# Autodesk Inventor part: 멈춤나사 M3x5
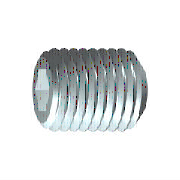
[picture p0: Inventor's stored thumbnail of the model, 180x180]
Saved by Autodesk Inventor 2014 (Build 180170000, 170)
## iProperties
Created: 2012-02
Part Number: 멈춤나사 M3x5
Material: 강철, 연강
Description: 6각 소켓 머리 없는 멈춤 나사
Document SubType Name: Modeling
Standard: KS B 1028
Designer: mduedu
Standards Organization: KS
Language: ko-KR
Size Designation: 납작점M3x5
Categories: <MemberInstance><Categories><Category DisplayName="조임쇠" InternalName="e4da775c-781d-43d5-af7c-5136215cf5a6" Mnemonic="FSTN"><Category DisplayName="볼트" InternalN
Density: 1 g/cm^3
Appearance: 노란색
IsCustomPart: 1
Author: mduedu
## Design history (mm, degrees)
sketch "스케치1"
  geometry: L1 (0, 0)-(2.5, 0); L2 (5, 0.866)-(5, 1.5); L3 (5, 1.5)-(0, 1.5); L4 (5, 0.866)-(3, 0.866); L5 (3, 0.866)-(2.5, 0); L6 (0, -0.3)-(0, 1.8) reference; L7 (0, 1.5)-(0, 0)
  constraints: 13 end point, 3 parallel, 1 collinear, 1 perpendicular, 1 point on line
  dimensions: "d0" = 2 distance of L2.start L4.end (= INTI); "d1" = 60 deg angle of L5 L1; "d2" = 3 diameter of L3 L1 (= NND); "d3" = 1.73205 diameter of L4 L1 (= 1.1547 x SW); "d5" = 5 distance from line of L2 L3.end (= NLG)
revolve "본체" sketch "스케치1" stored, may be unused: angle "d6" = 90 deg
sketch "스케치2"
  geometry: L1 (-0.433, 0.75)-(0.433, 0.75); L2 (0.433, 0.75)-(0.866, 0); L3 (0.866, 0)-(0.433, -0.75); L4 (0.433, -0.75)-(-0.433, -0.75); L5 (-0.433, -0.75)-(-0.866, 0); L6 (-0.866, 0)-(-0.433, 0.75); A1 r 0.866 centre (0, 0) between (-0.433, 0.75) and (0.433, 0.75) reference; 2 further points
  constraints: 12 end point, 2 point on circle, 1 coincident, 1 horizontal, 11 other
extrude "슬롯" join sketch "스케치2" taper "d9" = 0 deg; stored distance "d21" = 10
workaxis "Work Axis1"
workplane "Work Plane1"
body "Solid1"
chamfer "모따기1" distance "d7" = 0.30673 (= -0.5 x GD1 + 0.5 x NND); stored, may be unused: angle "d8" = 45 deg (= FAWI), second distance "d29" = 0.30673 (= -0.5 x GD1 + 0.5 x NND)
feature "스레드" dims "d11" = 5 (= NLG), "d12" = 0
chamfer "모따기2" distance "d13" = 0.30673 (= -0.5 x GD1 + 0.5 x NND); stored, may be unused: angle "d14" = 45 deg (= FAWI), second distance "d30" = 0.30673 (= -0.5 x GD1 + 0.5 x NND)
other parameters: "NND" = 3 [user parameter; used in 5 equation terms], "NLG" = 5 [user parameter; used in 2 equation terms], "INTI" = 2 [user parameter; used in 1 equation term], "FAWI" = 45 deg [user parameter; used in 2 equation terms], "SW" = 1.5 [user parameter; used in 2 equation terms], "GD1" = 2.38655 (= THREADDIA - 1.2269 x PTC) [user parameter; used in 4 equation terms], "d4" = 0, "FAWI1" = 45 deg [user parameter], "d15" = 0, "d31" = 0, "GUL" = 0.30673 (= 0.61345 x PTC) [user parameter], "SPD" = 2 [user parameter], "TOA" = 30 deg [user parameter], "THREADDIA" = 3 [user parameter; used in 1 equation term], "PTC" = 0.5 [user parameter; used in 4 equation terms], "GAL" = 0.30673 (= 0.61345 x PTC) [user parameter], "E0" = 1.7325 (= 1.155 x SW) [user parameter]
